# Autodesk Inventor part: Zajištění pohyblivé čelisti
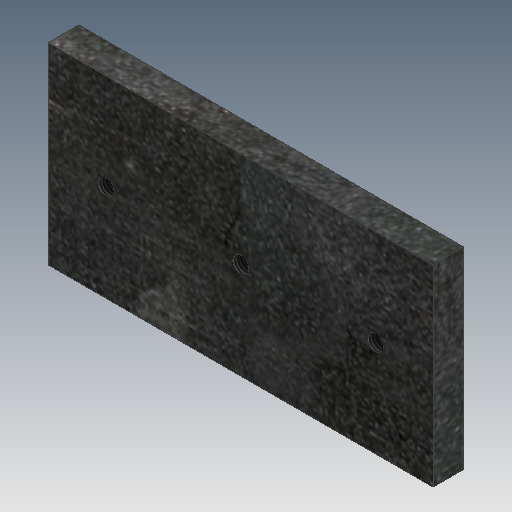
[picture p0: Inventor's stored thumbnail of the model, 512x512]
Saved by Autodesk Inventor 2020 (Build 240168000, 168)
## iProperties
Created: 2025-03
Part Number: Zajištění pohyblivé čelisti
Material: Ocel
Document SubType Name: Modeling
Designer: doma
Density: 7.85 g/cm^3
Appearance: Plech
Mass: 311.471 g
Surface Area: 126.312 cm^2
Volume: 39.6779 cm^3
Author: doma
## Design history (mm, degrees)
sketch "Náčrt1"
  geometry: L1 (-50, -25)-(50, -25); L2 (50, -25)-(50, 25); L3 (50, 25)-(-50, 25); L4 (-50, 25)-(-50, -25); L5 (-50, -25)-(50, 25); L6 (50, -25)-(-50, 25); 1 further point
  constraints: 12 end point, 2 midpoint, 2 parallel, 1 horizontal, 1 perpendicular
  dimensions: "d0" = 100 distance of L3.end L2.end; "d1" = 50 distance of L2.end L1.end
extrude "Vysunutí1" new body sketch "Náčrt1" distance "d2" = 8; taper "d3" = 0 deg
sketch "Náčrt2"
  geometry: 4 further points
  constraints: 1 coincident
  dimensions: "d4" = 35 distance of point (0, 0) point (-35, 0); "d5" = 35 distance of point (35, 0) point (0, 0)
hole "Díra1" sketch "Náčrt2" at (0, 0), (35, 0), (-35, 0) diameter "d6" = 4.134; stored, may be unused: countersink angle "d10" = 90 deg, drill point angle "d12" = 118 deg; dims "d7" = 10, "d8" = 4, "d9" = 2, "d11" = 8
node "Těleso1"
